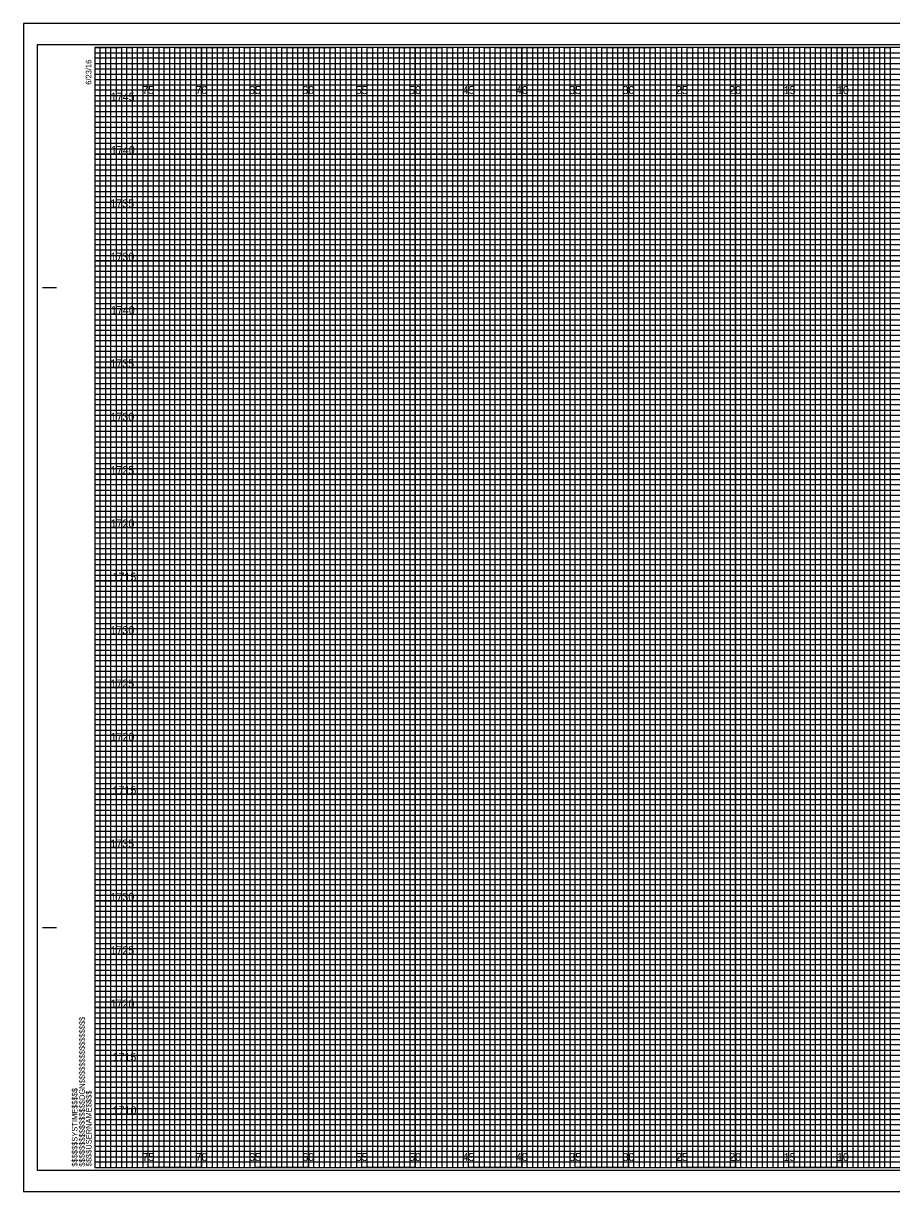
# Model space of a CAD drawing. Extents: x -7 to 162, y -2 to 107.
# Drawn here: x -6.7 to 74.6, y -2.3 to 107.3 of the extents above; entities that cross this region are included whole.
import ezdxf

# ---------------------------------------------------------------- set-up
doc = ezdxf.new("R2010")
doc.units = 0
for name, color, linetype in [('Raster_Level_0', 7, 'Continuous'), ('Scratch_Level_3', 7, 'Continuous'), ('Sheet Cross Section CELL', 7, 'Continuous'), ('Sheet Cross Section Grid Major CELL', 7, 'Continuous'), ('Sheet Cross Section Grid Middle CELL', 7, 'Continuous'), ('Sheet Cross Section Grid Minor 1 CELL', 7, 'Continuous'), ('Sheet Cross Section Grid Minor 2 CELL', 7, 'Continuous'), ('Sheet Cutting Line CELL', 7, 'Continuous'), ('Sheet DOT Grid CELL', 7, 'Continuous'), ('Sheet Plot Border Inside CELL', 7, 'Continuous'), ('Sheet Plot Border Outside CELL', 7, 'Continuous')]:
    doc.layers.add(name, color=color, linetype=linetype)

msp = doc.modelspace()

# ---------------------------------------------------------------- linework, layer by layer
at = {"layer": 'Sheet Cross Section CELL'}
for p, q in [((-4.9, 82.5), (-3.65, 82.5)), ((-4.85, 82.5), (-3.6, 82.5)), ((-4.9, 22.5), (-3.65, 22.5)), ((-4.85, 22.5), (-3.6, 22.5)), ((0, 0), (0, 0)), ((0, 0), (0, 0)), ((0, 0), (0, 0)), ((0, 0), (0, 0)), ((0, 0), (0, 0)), ((0, 0), (0, 0)), ((0, 0), (0, 0))]:
    msp.add_line(p, q, dxfattribs=at)
msp.add_lwpolyline([(160, 105), (0, 105), (0, 0), (160, 0)], close=True, dxfattribs=at)
at = {"layer": 'Sheet Cross Section Grid Major CELL'}
for p, q in [((5, 105), (0, 105)), ((5, 0), (5, 105)), ((15, 105), (10, 105)), ((10, 105), (10, 0)), ((15, 0), (15, 105)), ((25, 105), (20, 105)), ((20, 105), (20, 0)), ((25, 0), (25, 105)), ((35, 105), (30, 105)), ((30, 105), (30, 0)), ((35, 0), (35, 105)), ((45, 105), (40, 105)), ((40, 105), (40, 0)), ((45, 0), (45, 105)), ((55, 105), (50, 105)), ((50, 105), (50, 0)), ((55, 0), (55, 105)), ((65, 105), (60, 105)), ((60, 105), (60, 0)), ((65, 0), (65, 105)), ((75, 105), (70, 105)), ((70, 105), (70, 0)), ((10, 0), (5, 0)), ((20, 0), (15, 0)), ((30, 0), (25, 0)), ((40, 0), (35, 0)), ((50, 0), (45, 0)), ((60, 0), (55, 0)), ((70, 0), (65, 0))]:
    msp.add_line(p, q, dxfattribs=at)
for points in [[(0, 100), (160, 100), (160, 95), (0, 95)], [(0, 90), (160, 90), (160, 85), (0, 85)], [(0, 80), (160, 80), (160, 75), (0, 75)], [(0, 70), (160, 70), (160, 65), (0, 65)], [(0, 60), (160, 60), (160, 55), (0, 55)], [(0, 50), (160, 50), (160, 45), (0, 45)], [(0, 40), (160, 40), (160, 35), (0, 35)], [(0, 30), (160, 30), (160, 25), (0, 25)], [(0, 20), (160, 20), (160, 15), (0, 15)], [(0, 10), (160, 10), (160, 5), (0, 5)]]:
    msp.add_lwpolyline(points, dxfattribs=at)
at = {"layer": 'Sheet Cross Section Grid Middle CELL'}
for points in [[(0, 105), (2.5, 105), (2.5, 0), (7.5, 0), (7.5, 105), (12.5, 105), (12.5, 0), (17.5, 0), (17.5, 105), (22.5, 105), (22.5, 0), (27.5, 0), (27.5, 105), (32.5, 105), (32.5, 0), (37.5, 0), (37.5, 105), (42.5, 105), (42.5, 0), (47.5, 0), (47.5, 105), (52.5, 105), (52.5, 0), (57.5, 0), (57.5, 105), (62.5, 105), (62.5, 0), (67.5, 0), (67.5, 105), (72.5, 105), (72.5, 0), (77.5, 0)], [(0, 102.5), (137.5, 102.5)], [(0, 92.5), (160, 92.5), (160, 97.5), (0, 97.5)], [(0, 82.5), (160, 82.5), (160, 87.5), (0, 87.5)], [(0, 72.5), (160, 72.5), (160, 77.5), (0, 77.5)], [(0, 62.5), (160, 62.5), (160, 67.5), (0, 67.5)], [(0, 52.5), (160, 52.5), (160, 57.5), (0, 57.5)], [(0, 42.5), (160, 42.5), (160, 47.5), (0, 47.5)], [(0, 32.5), (160, 32.5), (160, 37.5), (0, 37.5)], [(0, 22.5), (160, 22.5), (160, 27.5), (0, 27.5)], [(0, 12.5), (160, 12.5), (160, 17.5), (0, 17.5)], [(0, 2.5), (160, 2.5), (160, 7.5), (0, 7.5)]]:
    msp.add_lwpolyline(points, dxfattribs=at)
at = {"layer": 'Sheet Cross Section Grid Minor 1 CELL'}
for p, q in [((0, 104.5), (130, 104.5)), ((130, 103.99), (0, 103.99)), ((0, 103.99), (0, 103.5)), ((0, 103.5), (130, 103.5)), ((130, 102.95), (0, 102.95)), ((0, 102.95), (0, 102)), ((0, 102), (160, 102))]:
    msp.add_line(p, q, dxfattribs=at)
for points in [[(0, 101.5), (135, 101.5), (160, 101.5), (160, 101), (0, 101)], [(0, 100.5), (160, 100.5), (160, 99.5), (0, 99.5)], [(0, 99), (160, 99), (160, 98.5), (0, 98.49)], [(0, 98), (160, 98), (160, 97), (0, 97)], [(0, 96.5), (160, 96.5), (160, 96), (0, 96)], [(0, 95.5), (160, 95.5), (160, 94.5), (0, 94.5)], [(0, 94), (160, 94), (160, 93.5), (0, 93.5)], [(0, 93), (160, 93), (160, 92), (0, 92)], [(0, 91.5), (160, 91.5), (160, 91), (0, 91)], [(0, 90.5), (160, 90.5), (160, 89.5), (0, 89.5)], [(0, 89), (160, 89), (160, 88.5), (0, 88.5)], [(0, 88), (160, 88), (160, 86.98), (160, 86.5), (160, 86), (0, 86)], [(0, 87), (160, 87), (160, 86.5), (0, 86.5)], [(0, 85.5), (160, 85.5), (160, 84.5), (0, 84.52)], [(0, 84.52), (160, 84.5), (160, 84), (0, 84)], [(0, 83.5), (160, 83.5), (160, 83), (0, 83)], [(0, 82), (160, 82), (160, 81.5), (0, 81.5)], [(0, 81), (160, 81), (160, 80.5), (0, 80.5)], [(-0.04, 79.45), (160, 79.45), (160, 78.94), (-0.04, 78.94)], [(0, 78.5), (160, 78.5), (160, 78), (0, 78)], [(0, 77), (160, 77), (160, 76.5), (0, 76.5)], [(0, 76), (160, 76), (160, 75.5), (0, 75.5)], [(0, 74.5), (160, 74.5), (160, 74), (0, 74)], [(0, 73.5), (160, 73.5), (160, 73), (0, 73)], [(0, 72), (160, 72), (160, 71.5), (0, 71.5)], [(0, 71), (160, 71), (160, 70.5), (0, 70.5)], [(0, 69.5), (160, 69.5), (160, 68.99), (0, 69)], [(0, 68.5), (160, 68.5), (160, 68), (0, 68)], [(0, 67), (160, 67), (160, 66.5), (0, 66.5)], [(0, 66), (160, 66), (160, 65.5), (0, 65.5)], [(0, 64.5), (160, 64.5), (160, 64), (0, 64)], [(0, 63.5), (160, 63.5), (160, 63), (0, 63)], [(0, 62), (160, 62), (160, 61.5), (0, 61.5)], [(0, 61), (160, 61), (160, 60.5), (0, 60.5)], [(0, 59.5), (160, 59.5), (160, 59), (0, 59)], [(0, 58.5), (160.03, 58.45), (160, 58), (0, 58)], [(0, 57), (160, 57), (160, 56.5), (0, 56.5)], [(0, 56), (160, 56), (160, 55.5), (0, 55.5)], [(0, 54.5), (160, 54.5), (160, 54), (0, 54)], [(0, 53.5), (160, 53.5), (160, 53), (0, 53)], [(0, 52), (160, 52), (160, 51.5), (0, 51.5)], [(0, 51), (160, 51), (160, 50.5), (0, 50.5)], [(0, 49.5), (160, 49.5), (160, 49), (0, 49)], [(0, 48.5), (160, 48.5), (160, 48), (0, 48)], [(0, 47), (160, 47), (160, 46.5), (0, 46.5)], [(0, 46), (160, 46), (160, 45.5), (0, 45.5)], [(0, 44.5), (160, 44.5), (160, 44), (0, 44)], [(0, 43.5), (160, 43.5), (160, 43), (0, 43)], [(0, 42), (160, 42), (160, 41.5), (0, 41.5)], [(0, 41), (160, 41), (160, 40.5), (0, 40.5)], [(0, 39.5), (160, 39.5), (160, 38.99), (0, 39)], [(0, 38.5), (160, 38.5), (160, 38), (0, 38)], [(0, 37), (160, 37), (160, 36.5), (0, 36.5)], [(0, 36), (160, 36), (160, 35.5), (0, 35.5)], [(0, 34.5), (160, 34.5), (160, 34), (0, 34)], [(0, 33.5), (160, 33.5), (160, 33), (0, 33)], [(0, 32), (160, 32), (160, 31.5), (0, 31.5)], [(0, 31), (160, 31), (160, 30.5), (0, 30.5)], [(0, 29.5), (160, 29.5), (160, 29), (0, 29)], [(0, 28.5), (160.03, 28.46), (160, 28), (0, 28)], [(0, 27), (160, 27), (160, 26.5), (0, 26.5)], [(0, 26), (160, 26), (160, 25.5), (0, 25.5)], [(0, 24.5), (160, 24.5), (160, 24), (0, 24)], [(0, 23.5), (160, 23.5), (160, 23), (0, 23)], [(0, 22), (160, 22), (160, 21.5), (0, 21.5)], [(0, 21), (160, 21), (160, 20.5), (0, 20.5)], [(0, 19.5), (160, 19.5), (160, 19), (0, 19)], [(0, 18.5), (160, 18.5), (160, 18), (0, 18)], [(0, 17), (160, 17), (160, 16.5), (0, 16.5)], [(0, 16), (160, 16), (160, 15.5), (0, 15.5)], [(0, 14.5), (160, 14.5), (160, 14), (0, 14)], [(0, 13.5), (160, 13.5), (160, 13), (0, 13)], [(0, 12), (160, 12), (160, 11.5), (0, 11.5)], [(0, 11), (160, 11), (160, 10.5), (0, 10.5)], [(0, 9.5), (160, 9.5), (160, 9), (0, 9)], [(0, 8.5), (160, 8.5), (160, 8), (0, 8)], [(0, 7), (160, 7), (160, 6.5), (0, 6.5)], [(0, 6), (160, 6), (160, 5.5), (0, 5.5)], [(0, 4.5), (160, 4.5), (160, 4), (0, 4)], [(0, 3.5), (160, 3.5), (160, 3), (0, 3)], [(0, 2), (160, 2), (160, 1.5), (0, 1.5)], [(0, 1), (160, 1), (160, 0.5), (0, 0.5)]]:
    msp.add_lwpolyline(points, dxfattribs=at)
at = {"layer": 'Sheet Cross Section Grid Minor 2 CELL'}
for points in [[(0, 0), (0.5, 0), (0.5, 105), (1, 105), (1, 0)], [(1, 0), (1.5, 0), (1.5, 105), (2, 105), (2, 0)], [(2.5, 0), (3, 0), (3, 105), (3.5, 105), (3.5, 0)], [(3.5, 0), (4, 0), (4, 105), (4.5, 105), (4.5, 0)], [(5, 0), (5.5, 0), (5.5, 105), (6, 105), (6, 0)], [(6, 0), (6.5, 0), (6.5, 105), (7, 105), (7, 0)], [(7.5, 0), (8, 0), (8, 105), (8.5, 105), (8.5, 0)], [(8.5, 0), (9, 0), (9, 105), (9.5, 105), (9.5, 0)], [(10, 0), (10.5, 0), (10.5, 105), (11, 105), (11, 0)], [(11, 0), (11.5, 0), (11.5, 105), (12, 105), (12, 0)], [(12.5, 0), (13, 0), (13, 105), (13.5, 105), (13.5, 0)], [(13.5, 0), (14, 0), (14, 105), (14.5, 105), (14.5, 0)], [(15, 0), (15.5, 0), (15.5, 105), (16, 105), (16, 0)], [(16, 0), (16.5, 0), (16.5, 105), (17, 105), (17, 0)], [(17.5, 0), (18, 0), (18, 105), (18.5, 105), (18.5, 0)], [(18.5, 0), (19, 0), (19, 105), (19.5, 105), (19.5, 0)], [(20, 0), (20.5, 0), (20.5, 105), (21, 105), (21, 0)], [(21, 0), (21.5, 0), (21.5, 105), (22, 105), (22, 0)], [(22.5, 0), (23, 0), (23, 105), (23.5, 105), (23.5, 0)], [(23.5, 0), (24, 0), (24, 105), (24.5, 105), (24.5, 0)], [(25, 0), (25.5, 0), (25.5, 105), (26, 105), (26, 0)], [(26, 0), (26.5, 0), (26.5, 105), (27, 105), (27, 0)], [(27.5, 0), (28, 0), (28, 105), (28.5, 105), (28.5, 0)], [(28.5, 0), (29, 0), (29, 105), (29.5, 105), (29.5, 0)], [(30, 0), (30.5, 0), (30.5, 105), (31, 105), (31, 0)], [(31, 0), (31.5, 0), (31.5, 105), (32, 105), (32, 0)], [(32.5, 0), (33, 0), (33, 105), (33.5, 105), (33.5, 0)], [(33.5, 0), (34, 0), (34, 105), (34.5, 105), (34.5, 0)], [(35, 0), (35.5, 0), (35.5, 105), (36, 105), (36, 0)], [(36, 0), (36.5, 0), (36.5, 105), (37, 105), (37, 0)], [(37.5, 0), (38, 0), (38, 105), (38.5, 105), (38.5, 0)], [(38.5, 0), (39, 0), (39, 105), (39.5, 105), (39.5, 0)], [(40, 0), (40.5, 0), (40.5, 105), (41, 105), (41, 0)], [(41, 0), (41.5, 0), (41.5, 105), (42, 105), (42, 0)], [(42.5, 0), (43, 0), (43, 105), (43.5, 105), (43.5, 0)], [(43.5, 0), (44, 0), (44, 105), (44.5, 105), (44.5, 0)], [(45, 0), (45.5, 0), (45.5, 105), (46, 105), (46, 0)], [(46, 0), (46.5, 0), (46.5, 105), (47, 105), (47, 0)], [(47.5, 0), (48, 0), (48, 105), (48.5, 105), (48.5, 0)], [(48.5, 0), (49, 0), (49, 105), (49.5, 105), (49.5, 0)], [(50, 0), (50.5, 0), (50.5, 105), (51, 105), (51, 0)], [(51, 0), (51.5, 0), (51.5, 105), (52, 105), (52, 0)], [(52.5, 0), (53, 0), (53, 105), (53.5, 105), (53.5, 0)], [(53.5, 0), (54, 0), (54, 105), (54.5, 105), (54.5, 0)], [(55, 0), (55.5, 0), (55.5, 105), (56, 105), (56, 0)], [(56, 0), (56.5, 0), (56.5, 105), (57, 105), (57, 0)], [(57.5, 0), (58, 0), (58, 105), (58.5, 105), (58.5, 0)], [(58.5, 0), (59, 0), (59, 105), (59.5, 105), (59.5, 0)], [(60, 0), (60.5, 0), (60.5, 105), (61, 105), (61, 0)], [(61, 0), (61.5, 0), (61.5, 105), (62, 105), (62, 0)], [(62.5, 0), (63, 0), (63, 105), (63.5, 105), (63.5, 0)], [(63.5, 0), (64, 0), (64, 105), (64.5, 105), (64.5, 0)], [(65, 0), (65.5, 0), (65.5, 105), (66, 105), (66, 0)], [(66, 0), (66.5, 0), (66.5, 105), (67, 105), (67, 0)], [(67.5, 0), (68, 0), (68, 105), (68.5, 105), (68.5, 0)], [(68.5, 0), (69, 0), (69, 105), (69.5, 105), (69.5, 0)], [(70, 0), (70.5, 0), (70.5, 105), (71, 105), (71, 0)], [(71, 0), (71.5, 0), (71.5, 105), (72, 105), (72, 0)], [(72.5, 0), (73, 0), (73, 105), (73.5, 105), (73.5, 0)], [(73.5, 0), (74, 0), (74, 105), (74.5, 105), (74.5, 0)]]:
    msp.add_lwpolyline(points, dxfattribs=at)
at = {"layer": 'Sheet Cutting Line CELL'}
for p, q in [((161.65, 107.25), (-6.7, 107.25)), ((-6.7, 107.25), (-6.7, -2.25)), ((-6.7, -2.25), (161.65, -2.25))]:
    msp.add_line(p, q, dxfattribs=at)
at = {"layer": 'Sheet DOT Grid CELL'}
for p, q in [((5, 0), (5, 105)), ((10, 0), (10, 105)), ((15, 0), (15, 105)), ((20, 0), (20, 105)), ((25, 0), (25, 105)), ((30, 0), (30, 105)), ((35, 0), (35, 105)), ((40, 0), (40, 105)), ((45, 0), (45, 105)), ((50, 0), (50, 105)), ((55, 0), (55, 105)), ((60, 0), (60, 105)), ((65, 0), (65, 105)), ((70, 0), (70, 105)), ((0, 100), (160, 100)), ((0, 95), (160, 95)), ((0, 90), (160, 90)), ((0, 85), (160, 85)), ((0, 80), (160, 80)), ((0, 75), (160, 75)), ((0, 70), (160, 70)), ((0, 65), (160, 65)), ((0, 60), (160, 60)), ((0, 55), (160, 55)), ((0, 50), (160, 50)), ((0, 45), (160, 45)), ((0, 40), (160, 40)), ((0, 35), (160, 35)), ((0, 30), (160, 30)), ((0, 25), (160, 25)), ((0, 20), (160, 20)), ((0, 15), (160, 15)), ((0, 10), (160, 10)), ((0, 5), (160, 5))]:
    msp.add_line(p, q, dxfattribs=at)
at = {"layer": 'Sheet Plot Border Inside CELL'}
msp.add_lwpolyline([(-5.4, -0.25), (161.2, -0.25), (161.2, 105.25), (-5.4, 105.25)], close=True, dxfattribs=at)
at = {"layer": 'Sheet Plot Border Outside CELL'}
msp.add_lwpolyline([(-6.7, -2.25), (161.65, -2.25), (161.65, 107.25), (-6.7, 107.25)], close=True, dxfattribs=at)

# ---------------------------------------------------------------- texts
at = {"layer": 'Raster_Level_0'}
for s, p in [('75', (4.44, 100.62)), ('70', (9.43, 100.62)), ('65', (14.44, 100.62)), ('60', (19.43, 100.62)), ('55', (24.44, 100.62)), ('50', (29.43, 100.62)), ('45', (34.44, 100.62)), ('40', (39.43, 100.62)), ('35', (44.44, 100.62)), ('30', (49.43, 100.62)), ('25', (54.44, 100.62)), ('20', (59.43, 100.62)), ('15', (64.53, 100.62)), ('10', (69.52, 100.62)), ('75', (4.44, 0.62)), ('70', (9.43, 0.62)), ('65', (14.44, 0.62)), ('60', (19.43, 0.62)), ('55', (24.44, 0.62)), ('50', (29.43, 0.62)), ('45', (34.44, 0.62)), ('40', (39.43, 0.62)), ('35', (44.44, 0.62)), ('30', (49.43, 0.62)), ('25', (54.44, 0.62)), ('20', (59.43, 0.62)), ('15', (64.53, 0.62)), ('10', (69.52, 0.62))]:
    msp.add_text(s, height=0.75, dxfattribs=at).set_placement(p)
at = {"layer": 'Scratch_Level_3'}
for s, p in [('1745', (1.49, 100)), ('1740', (1.5, 95)), ('1735', (1.45, 90)), ('1730', (1.46, 85)), ('1740', (1.5, 80)), ('1735', (1.45, 75)), ('1730', (1.46, 70)), ('1725', (1.46, 65)), ('1720', (1.47, 60)), ('1715', (1.65, 55)), ('1730', (1.46, 50)), ('1725', (1.46, 45)), ('1720', (1.47, 40)), ('1715', (1.65, 35)), ('1735', (1.45, 30)), ('1730', (1.46, 25)), ('1725', (1.46, 20)), ('1720', (1.47, 15)), ('1715', (1.65, 10)), ('1710', (1.66, 5))]:
    msp.add_text(s, height=0.75, dxfattribs=at).set_placement(p)
at = {"layer": 'Sheet Cross Section CELL'}
for s, p in [('6/23/16', (-0.33, 101.5)), ('$$$$$$$$$$$$$$$$DGN$$$$$$$$$$$$$$$$', (-0.94, 0.09)), ('$$$$$$SYSTIME$$$$$', (-1.63, 0.09)), ('$$$$USERNAME$$$$', (-0.31, 0.12))]:
    msp.add_text(s, height=0.525, rotation=90, dxfattribs=at).set_placement(p)

doc.saveas('drawing.dxf')
